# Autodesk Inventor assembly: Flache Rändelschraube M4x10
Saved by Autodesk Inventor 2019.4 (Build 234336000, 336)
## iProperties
Created: 2021-06
Part Number: Flache Rändelschraube M4x10
Document SubType Name: Assembly
Designer: Administrator
Title: Flache Rändelschraube M4x10 v2
Author: Administrator
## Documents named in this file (2)
- c:\worker\convert-fusion-r04\tmp\job-1\39\output\files\e1e84fd7-b652-4e3d-a1c7-f0a54bbc30a7\Flache Rändelschraube M4x10 v2_1.iam
- c:\worker\convert-fusion-r04\tmp\job-1\39\output\files\e1e84fd7-b652-4e3d-a1c7-f0a54bbc30a7\_Flat knurled screw DIN 653-M4-10-ZB.ipt
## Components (1 placed, 1 different names)
1. _Flat knurled screw DIN 653-M4-10-ZB:1
